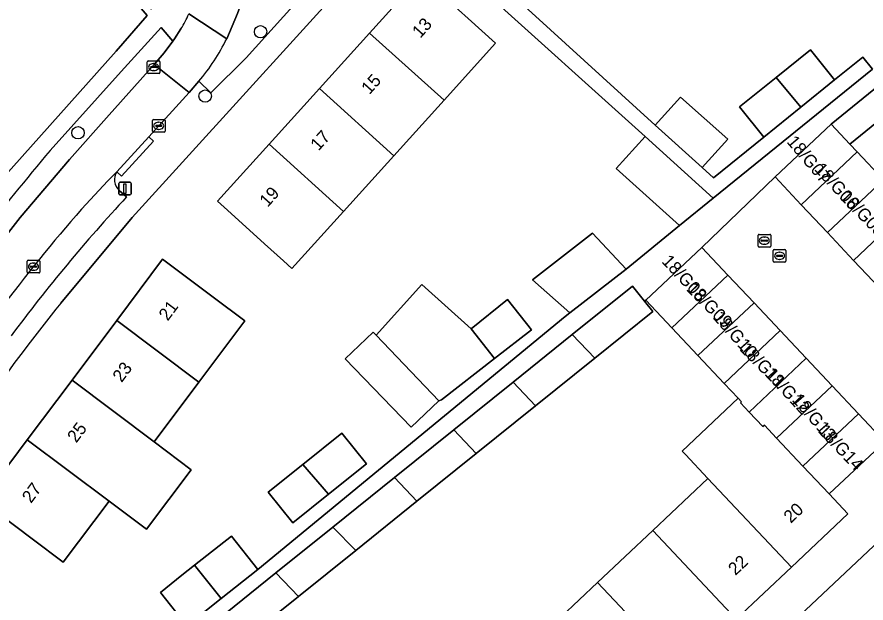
# Model space of a CAD drawing. Extents: x 161881 to 162523, y 381678 to 382381.
# Drawn here: x 162309.8 to 162377, y 381824.1 to 381870.4 of the extents above; entities that cross this region are included whole.
import ezdxf

# ---------------------------------------------------------------- set-up
doc = ezdxf.new("R2010")
doc.units = 0
for name, color, linetype in [('IMGEO_Boom', 7, 'Continuous'), ('IMGEO_Erf', 7, 'Continuous'), ('IMGEO_Groenvoorziening', 7, 'Continuous'), ('IMGEO_Kolk', 7, 'Continuous'), ('IMGEO_Lichtmast', 7, 'Continuous'), ('IMGEO_Pand', 7, 'Continuous'), ('IMGEO_Pand_nummerreeks', 7, 'Continuous'), ('IMGEO_Parkeervlak_open', 7, 'Continuous'), ('IMGEO_Rijbaan_lokaal_open', 7, 'Continuous'), ('IMGEO_Rioolput', 7, 'Continuous'), ('IMGEO_Voetpad_open', 7, 'Continuous')]:
    doc.layers.add(name, color=color, linetype=linetype)

msp = doc.modelspace()

# ---------------------------------------------------------------- linework, layer by layer
at = {"layer": 'IMGEO_Boom'}
for centre in [(162329.077, 381869.231), (162324.693, 381864.143), (162314.637, 381861.242)]:
    msp.add_circle(centre, 0.489, dxfattribs=at)
at = {"layer": 'IMGEO_Erf'}
for points in [[(162308.695, 381857.661), (162317.651, 381867.68), (162320.093, 381870.515), (162317.508, 381873.557), (162311.416, 381880.988), (162315.774, 381884.648), (162315.994, 381884.379), (162316.488, 381884.836), (162316.601, 381884.938), (162316.382, 381885.179), (162318.764, 381887.154), (162318.965, 381886.995), (162319.543, 381887.466), (162319.343, 381887.695), (162320.508, 381888.575), (162315.645, 381894.334), (162318.477, 381896.725), (162315.068, 381901.394), (162281.55, 381876.921), (162275.507, 381885.197)], [(162353.161, 381846.707), (162353.543, 381847.003), (162350.598, 381849.61), (162355.321, 381853.31), (162357.989, 381850.459), (162362.211, 381853.895), (162357.206, 381858.415), (162359.495, 381860.949), (162346.556, 381872.633), (162340.416, 381878.177), (162318.912, 381854.529), (162313.274, 381847.757)], [(162350.544, 381870.731), (162360.3, 381861.84), (162362.297, 381864.051), (162366.048, 381860.746), (162364.011, 381858.49), (162364.905, 381857.683), (162368.889, 381860.901), (162366.965, 381863.284), (162369.857, 381865.619), (162372.561, 381867.803), (162374.485, 381865.419), (162376.709, 381867.214), (162377.479, 381866.261)], [(162380.326, 381864.115), (162375.677, 381860.351), (162376.269, 381859.723), (162378.341, 381857.522)], [(162351.368, 381821.57), (162355.733, 381825.68), (162360.097, 381829.79), (162364.461, 381833.9), (162362.678, 381835.792), (162362.428, 381836.059), (162366.847, 381840.247), (162365.739, 381841.424), (162363.673, 381843.618), (162361.607, 381845.811), (162359.541, 381848.005), (162359.452, 381847.933), (162360.114, 381847.11), (162355.504, 381843.404), (162350.817, 381839.636), (162346.13, 381835.868), (162341.444, 381832.1), (162336.598, 381828.204), (162332.07, 381824.564), (162327.383, 381820.796)], [(162323.239, 381822.253), (162321.148, 381824.898), (162322.854, 381826.247), (162323.856, 381827.039), (162326.779, 381829.352), (162328.871, 381826.707), (162353.161, 381846.707)]]:
    msp.add_lwpolyline(points, dxfattribs=at)
for points in [[(162331.56, 381850.508), (162330.885, 381851.118), (162329.39, 381852.469), (162326.468, 381855.111), (162325.681, 381855.822), (162329.755, 381860.33), (162333.73, 381864.728), (162337.705, 381869.126), (162341.782, 381873.637), (162342.442, 381873.04), (162345.491, 381870.284), (162347.661, 381868.323), (162343.586, 381863.815), (162339.611, 381859.416), (162335.637, 381855.019)], [(162324.194, 381841.527), (162320.657, 381836.81), (162323.58, 381834.6), (162320.051, 381829.895), (162317.092, 381832.114), (162313.465, 381827.278), (162310.999, 381829.127), (162306.999, 381832.127), (162310.626, 381836.963), (162314.163, 381841.68), (162317.701, 381846.396), (162321.328, 381851.233), (162325.328, 381848.233), (162327.821, 381846.363)], [(162335.78, 381843.375), (162337.976, 381845.482), (162338.218, 381845.23), (162341.835, 381849.242), (162345.728, 381845.749), (162348.6, 381848.045), (162350.496, 381845.651), (162347.592, 381843.394), (162343.385, 381840.124), (162343.181, 381840.056), (162340.985, 381837.949)], [(162332.417, 381835.005), (162335.512, 381837.481), (162337.444, 381835.066), (162334.447, 381832.668), (162331.62, 381830.407), (162329.689, 381832.822)], [(162377.552, 381828.547), (162383.149, 381833.811), (162380.574, 381836.724), (162378.448, 381836.809), (162374.061, 381832.677), (162375.536, 381831.111), (162371.061, 381826.897), (162366.697, 381822.787), (162362.333, 381818.677), (162357.968, 381814.567), (162353.605, 381810.457), (162349.24, 381806.347), (162344.875, 381802.236), (162340.402, 381798.024), (162340.265, 381798.17), (162339.511, 381798.971), (162336.964, 381796.572), (162337.718, 381795.771), (162340.037, 381793.265)]]:
    msp.add_lwpolyline(points, close=True, dxfattribs=at)
msp.add_arc((162413.302, 381766.264), 129.022, 140.83, 149.413, dxfattribs=at)
at = {"layer": 'IMGEO_Groenvoorziening'}
for points in [[(162324.203, 381865.309), (162325.146, 381864.385), (162327.942, 381867.176), (162337.02, 381877.264)], [(162328.833, 381875.105), (162327.245, 381870.683), (162326.398, 381868.679)], [(162320.649, 381866.638), (162321.455, 381867.563), (162322.127, 381868.477), (162321.225, 381869.573), (162318.048, 381866.084), (162312.423, 381859.839)], [(162303.292, 381845.82), (162306.611, 381850.151), (162310.057, 381854.543), (162313.959, 381859.114), (162317.095, 381862.667), (162320.649, 381866.638)]]:
    msp.add_lwpolyline(points, dxfattribs=at)
for centre, radius, start, end in [((162310.747, 381876.474), 17.485, 320.31831, 333.52645), ((162591.617, 381627.062), 363.503, 140.18045, 142.96062)]:
    msp.add_arc(centre, radius, start, end, dxfattribs=at)
at = {"layer": 'IMGEO_Kolk'}
for p, q in [((162320.119, 381866.006), (162320.119, 381866.858)), ((162320.194, 381866.932), (162321.046, 381866.932)), ((162320.607, 381866.712), (162320.632, 381866.712)), ((162321.12, 381866.858), (162321.12, 381866.006)), ((162320.378, 381866.426), (162320.378, 381866.438)), ((162320.816, 381866.389), (162320.418, 381866.389)), ((162320.421, 381866.475), (162320.819, 381866.475)), ((162320.63, 381866.152), (162320.605, 381866.152)), ((162320.862, 381866.438), (162320.862, 381866.426)), ((162321.046, 381865.932), (162320.194, 381865.932)), ((162320.52, 381861.36), (162320.52, 381862.212)), ((162320.595, 381862.286), (162321.447, 381862.286)), ((162321.008, 381862.066), (162321.033, 381862.066)), ((162321.521, 381862.212), (162321.521, 381861.36)), ((162320.779, 381861.78), (162320.779, 381861.792)), ((162321.217, 381861.743), (162320.819, 381861.743)), ((162320.822, 381861.829), (162321.22, 381861.829)), ((162321.031, 381861.506), (162321.006, 381861.506)), ((162321.263, 381861.792), (162321.263, 381861.78)), ((162321.447, 381861.286), (162320.595, 381861.286)), ((162369.628, 381851.084), (162369.628, 381851.936)), ((162369.703, 381852.01), (162370.555, 381852.01)), ((162370.629, 381851.936), (162370.629, 381851.084)), ((162369.887, 381851.504), (162369.887, 381851.516)), ((162370.325, 381851.467), (162369.927, 381851.467)), ((162369.93, 381851.553), (162370.328, 381851.553)), ((162370.116, 381851.79), (162370.141, 381851.79)), ((162370.371, 381851.516), (162370.371, 381851.504)), ((162310.61, 381850.228), (162310.61, 381851.08)), ((162310.685, 381851.154), (162311.537, 381851.154)), ((162310.869, 381850.648), (162310.869, 381850.66)), ((162311.307, 381850.611), (162310.909, 381850.611)), ((162310.912, 381850.697), (162311.31, 381850.697)), ((162311.098, 381850.934), (162311.123, 381850.934)), ((162311.353, 381850.66), (162311.353, 381850.648)), ((162311.611, 381851.08), (162311.611, 381850.228)), ((162370.555, 381851.01), (162369.703, 381851.01)), ((162370.139, 381851.23), (162370.114, 381851.23)), ((162311.537, 381850.154), (162310.685, 381850.154)), ((162311.121, 381850.374), (162311.096, 381850.374))]:
    msp.add_line(p, q, dxfattribs=at)
for points in [[(162320.119, 381866.006), (162320.119, 381866.858)], [(162320.194, 381866.932), (162321.046, 381866.932)], [(162321.12, 381866.858), (162321.12, 381866.006)], [(162321.046, 381865.932), (162320.194, 381865.932)], [(162320.52, 381861.36), (162320.52, 381862.212)], [(162320.595, 381862.286), (162321.447, 381862.286)], [(162321.521, 381862.212), (162321.521, 381861.36)], [(162321.447, 381861.286), (162320.595, 381861.286)], [(162369.628, 381851.084), (162369.628, 381851.936)], [(162369.703, 381852.01), (162370.555, 381852.01)], [(162370.629, 381851.936), (162370.629, 381851.084)], [(162310.61, 381850.228), (162310.61, 381851.08)], [(162310.685, 381851.154), (162311.537, 381851.154)], [(162311.611, 381851.08), (162311.611, 381850.228)], [(162370.555, 381851.01), (162369.703, 381851.01)], [(162311.537, 381850.154), (162310.685, 381850.154)]]:
    msp.add_lwpolyline(points, dxfattribs=at)
for centre, radius, start, end in [((162320.196, 381866.856), 0.0765, 91.55205, 178.44795), ((162320.196, 381866.856), 0.0765, 91.55205, 178.44795), ((162321.044, 381866.856), 0.0765, 1.55205, 88.44795), ((162321.044, 381866.856), 0.0765, 1.55205, 88.44795), ((162320.418, 381866.435), 0.0403, 85.87752, 175.75265), ((162320.415, 381866.425), 0.0366, 178.93798, 274.71019), ((162320.819, 381866.432), 0.043, 264.86636, 352.45326), ((162320.823, 381866.437), 0.0386, 1.73085, 96.63898), ((162320.196, 381866.008), 0.0765, 181.55205, 268.44795), ((162320.196, 381866.008), 0.0765, 181.55205, 268.44795), ((162321.044, 381866.008), 0.0765, 271.55205, 358.44795), ((162321.044, 381866.008), 0.0765, 271.55205, 358.44795), ((162320.597, 381862.21), 0.0765, 91.55205, 178.44795), ((162320.597, 381862.21), 0.0765, 91.55205, 178.44795), ((162321.445, 381862.21), 0.0765, 1.55205, 88.44795), ((162321.445, 381862.21), 0.0765, 1.55205, 88.44795), ((162320.597, 381861.362), 0.0765, 181.55205, 268.44795), ((162320.597, 381861.362), 0.0765, 181.55205, 268.44795), ((162320.819, 381861.789), 0.0403, 85.87752, 175.75265), ((162320.816, 381861.779), 0.0366, 178.93798, 274.71019), ((162321.22, 381861.786), 0.043, 264.86636, 352.45326), ((162321.224, 381861.791), 0.0386, 1.73085, 96.63898), ((162321.445, 381861.362), 0.0765, 271.55205, 358.44795), ((162321.445, 381861.362), 0.0765, 271.55205, 358.44795), ((162369.705, 381851.934), 0.0765, 91.55205, 178.44795), ((162369.705, 381851.934), 0.0765, 91.55205, 178.44795), ((162370.553, 381851.934), 0.0765, 1.55205, 88.44795), ((162370.553, 381851.934), 0.0765, 1.55205, 88.44795), ((162369.927, 381851.513), 0.0403, 85.87752, 175.75265), ((162369.924, 381851.503), 0.0366, 178.93798, 274.71019), ((162370.328, 381851.51), 0.043, 264.86636, 352.45326), ((162370.332, 381851.515), 0.0386, 1.73085, 96.63898), ((162310.687, 381851.078), 0.0765, 91.55205, 178.44795), ((162310.687, 381851.078), 0.0765, 91.55205, 178.44795), ((162310.909, 381850.657), 0.0403, 85.87752, 175.75265), ((162310.906, 381850.647), 0.0366, 178.93798, 274.71019), ((162311.31, 381850.654), 0.043, 264.86636, 352.45326), ((162311.314, 381850.659), 0.0386, 1.73085, 96.63898), ((162311.535, 381851.078), 0.0765, 1.55205, 88.44795), ((162311.535, 381851.078), 0.0765, 1.55205, 88.44795), ((162369.705, 381851.086), 0.0765, 181.55205, 268.44795), ((162369.705, 381851.086), 0.0765, 181.55205, 268.44795), ((162370.553, 381851.086), 0.0765, 271.55205, 358.44795), ((162370.553, 381851.086), 0.0765, 271.55205, 358.44795), ((162310.687, 381850.23), 0.0765, 181.55205, 268.44795), ((162310.687, 381850.23), 0.0765, 181.55205, 268.44795), ((162311.535, 381850.23), 0.0765, 271.55205, 358.44795), ((162311.535, 381850.23), 0.0765, 271.55205, 358.44795)]:
    msp.add_arc(centre, radius, start, end, dxfattribs=at)
for centre, major_axis, ratio, start_param, end_param in [((162320.606, 381866.432), (-0.387, 0.002), 0.722429, 4.712389, 7.853982), ((162320.631, 381866.432), (-0.39, 0.002), 0.717154, 1.570796, 4.712389), ((162321.007, 381861.786), (-0.387, 0.002), 0.722429, 4.712389, 7.853982), ((162321.032, 381861.786), (-0.39, 0.002), 0.717154, 1.570796, 4.712389), ((162370.115, 381851.51), (-0.387, 0.002), 0.722429, 4.712389, 7.853982), ((162370.14, 381851.51), (-0.39, 0.002), 0.717154, 1.570796, 4.712389), ((162311.097, 381850.654), (-0.387, 0.002), 0.722429, 4.712389, 7.853982), ((162311.122, 381850.654), (-0.39, 0.002), 0.717154, 1.570796, 4.712389)]:
    msp.add_ellipse(centre, major_axis=major_axis, ratio=ratio, start_param=start_param, end_param=end_param, dxfattribs=at)
at = {"layer": 'IMGEO_Lichtmast'}
for p, q in [((162317.953, 381857.322), (162318.743, 381857.322)), ((162318.743, 381857.322), (162317.953, 381857.322)), ((162317.853, 381856.422), (162317.853, 381857.222)), ((162317.853, 381857.222), (162317.853, 381856.422)), ((162318.843, 381857.222), (162318.843, 381856.422)), ((162318.843, 381856.422), (162318.843, 381857.222)), ((162318.743, 381856.322), (162317.953, 381856.322)), ((162317.953, 381856.322), (162318.743, 381856.322))]:
    msp.add_line(p, q, dxfattribs=at)
msp.add_lwpolyline([(162318.273, 381857.197), (162318.423, 381857.197), (162318.423, 381856.447), (162318.273, 381856.447), (162318.273, 381857.197)], dxfattribs=at)
for centre, start, end in [((162317.953, 381857.222), 90, 180), ((162317.953, 381857.222), 90, 180), ((162318.743, 381857.222), 0, 90), ((162318.743, 381857.222), 360, 90), ((162317.953, 381856.422), 180, 270), ((162317.953, 381856.422), 180, 270), ((162318.743, 381856.422), 270, 0), ((162318.743, 381856.422), 270, 0)]:
    msp.add_arc(centre, 0.1, start, end, dxfattribs=at)
at = {"layer": 'IMGEO_Pand'}
for points in [[(162345.491, 381870.284), (162342.442, 381873.04), (162341.782, 381873.637), (162337.705, 381869.126), (162343.586, 381863.815), (162347.661, 381868.323)], [(162333.73, 381864.728), (162339.611, 381859.416), (162343.586, 381863.815), (162337.705, 381869.126)], [(162369.857, 381865.619), (162371.811, 381863.261), (162374.485, 381865.419), (162372.561, 381867.803)], [(162369.857, 381865.619), (162366.965, 381863.284), (162368.889, 381860.901), (162371.811, 381863.261)], [(162378.844, 381865.687), (162374.196, 381861.923), (162375.677, 381860.351), (162380.326, 381864.115)], [(162333.73, 381864.728), (162329.755, 381860.33), (162335.637, 381855.019), (162339.611, 381859.416)], [(162364.011, 381858.49), (162366.048, 381860.746), (162362.297, 381864.051), (162360.3, 381861.84)], [(162376.269, 381859.723), (162375.677, 381860.351), (162374.196, 381861.923), (162369.767, 381857.752), (162371.839, 381855.551)], [(162362.211, 381853.895), (162364.887, 381856.08), (162359.495, 381860.949), (162357.206, 381858.415)], [(162335.637, 381855.019), (162329.755, 381860.33), (162325.681, 381855.822), (162326.468, 381855.111), (162329.39, 381852.469), (162330.885, 381851.118), (162331.56, 381850.508)], [(162376.269, 381859.723), (162371.839, 381855.551), (162373.912, 381853.351), (162378.341, 381857.522)], [(162375.984, 381851.15), (162380.413, 381855.321), (162378.341, 381857.522), (162373.912, 381853.351)], [(162382.485, 381853.121), (162382.003, 381853.632), (162380.413, 381855.321), (162375.984, 381851.15), (162378.057, 381848.95)], [(162353.543, 381847.003), (162357.989, 381850.459), (162355.321, 381853.31), (162350.598, 381849.61)], [(162361.607, 381845.811), (162366.04, 381849.985), (162363.974, 381852.179), (162359.541, 381848.005)], [(162317.701, 381846.396), (162324.194, 381841.527), (162327.821, 381846.363), (162325.328, 381848.233), (162321.328, 381851.233)], [(162361.607, 381845.811), (162363.673, 381843.618), (162368.105, 381847.792), (162366.04, 381849.985)], [(162345.728, 381845.749), (162341.835, 381849.242), (162338.218, 381845.23), (162343.181, 381840.056), (162343.385, 381840.124), (162347.592, 381843.394)], [(162360.114, 381847.11), (162359.452, 381847.933), (162358.498, 381849.12), (162353.73, 381845.286), (162355.504, 381843.404)], [(162348.6, 381848.045), (162345.728, 381845.749), (162347.592, 381843.394), (162350.496, 381845.651)], [(162370.171, 381845.598), (162368.105, 381847.792), (162363.673, 381843.618), (162365.739, 381841.424)], [(162317.701, 381846.396), (162314.163, 381841.68), (162320.657, 381836.81), (162324.194, 381841.527)], [(162338.218, 381845.23), (162337.976, 381845.482), (162335.78, 381843.375), (162340.985, 381837.949), (162343.181, 381840.056)], [(162353.73, 381845.286), (162349.043, 381841.518), (162350.817, 381839.636), (162355.504, 381843.404)], [(162372.237, 381843.405), (162370.171, 381845.598), (162365.739, 381841.424), (162366.847, 381840.247), (162367.11, 381839.968), (162367.028, 381839.892), (162367.723, 381839.152)], [(162372.237, 381843.405), (162367.723, 381839.152), (162368.805, 381838.001), (162368.93, 381838.118), (162369.896, 381837.094), (162374.285, 381841.229)], [(162320.657, 381836.81), (162314.163, 381841.68), (162310.626, 381836.963), (162317.092, 381832.114), (162320.051, 381829.895), (162323.58, 381834.6)], [(162349.043, 381841.518), (162344.356, 381837.75), (162346.13, 381835.868), (162350.817, 381839.636)], [(162371.978, 381834.886), (162376.367, 381839.019), (162374.285, 381841.229), (162369.896, 381837.094)], [(162371.978, 381834.886), (162369.896, 381837.094), (162368.93, 381838.118), (162368.805, 381838.001), (162367.723, 381839.152), (162367.028, 381839.892), (162367.11, 381839.968), (162366.847, 381840.247), (162362.428, 381836.059), (162362.678, 381835.792), (162364.461, 381833.9), (162371.061, 381826.897), (162375.536, 381831.111), (162374.061, 381832.677)], [(162371.978, 381834.886), (162374.061, 381832.677), (162378.448, 381836.809), (162376.367, 381839.019)], [(162335.512, 381837.481), (162332.417, 381835.005), (162334.447, 381832.668), (162337.444, 381835.066)], [(162339.67, 381833.983), (162341.444, 381832.1), (162346.13, 381835.868), (162344.356, 381837.75)], [(162310.626, 381836.963), (162306.999, 381832.127), (162310.999, 381829.127), (162313.465, 381827.278), (162317.092, 381832.114)], [(162332.417, 381835.005), (162329.689, 381832.822), (162331.62, 381830.407), (162334.447, 381832.668)], [(162339.67, 381833.983), (162334.797, 381830.064), (162336.598, 381828.204), (162341.444, 381832.1)], [(162364.461, 381833.9), (162360.097, 381829.79), (162366.697, 381822.787), (162371.061, 381826.897)], [(162330.296, 381826.446), (162332.07, 381824.564), (162336.598, 381828.204), (162334.797, 381830.064)], [(162362.333, 381818.677), (162366.697, 381822.787), (162360.097, 381829.79), (162355.733, 381825.68)], [(162326.779, 381829.352), (162323.856, 381827.039), (162325.971, 381824.413), (162328.871, 381826.707)], [(162325.971, 381824.413), (162323.856, 381827.039), (162322.854, 381826.247), (162321.148, 381824.898), (162323.239, 381822.253)], [(162325.609, 381822.678), (162327.383, 381820.796), (162332.07, 381824.564), (162330.296, 381826.446)], [(162362.333, 381818.677), (162355.733, 381825.68), (162351.368, 381821.57), (162357.968, 381814.567)]]:
    msp.add_lwpolyline(points, close=True, dxfattribs=at)
at = {"layer": 'IMGEO_Parkeervlak_open'}
for points in [[(162317.714, 381858.155), (162316.997, 381857.442), (162314.904, 381855.188)], [(162318.479, 381856.168), (162317.896, 381856.676)]]:
    msp.add_lwpolyline(points, dxfattribs=at)
for centre, radius, start, end in [((162318.634, 381857.517), 1.119, 145.27106, 228.75959), ((162415.221, 381766.452), 131.939, 137.15809, 143.35927), ((162424.966, 381759.231), 146.019, 138.91675, 147.00635)]:
    msp.add_arc(centre, radius, start, end, dxfattribs=at)
at = {"layer": 'IMGEO_Rijbaan_lokaal_open'}
for points in [[(162323.403, 381870.644), (162326.398, 381868.679), (162327.245, 381870.683), (162328.833, 381875.105)], [(162326.398, 381868.679), (162323.403, 381870.644)], [(162322.78, 381869.453), (162322.262, 381868.661), (162322.127, 381868.477), (162321.455, 381867.563), (162320.649, 381866.638), (162323.422, 381864.435), (162324.203, 381865.309)], [(162314.904, 381855.188), (162316.997, 381857.442), (162317.714, 381858.155), (162320.231, 381860.917), (162323.422, 381864.435), (162320.649, 381866.638), (162317.095, 381862.667), (162313.959, 381859.114), (162310.057, 381854.543), (162306.611, 381850.151), (162303.292, 381845.82)], [(162377.552, 381828.547), (162340.037, 381793.265), (162339.247, 381792.69), (162337.86, 381791.68), (162337.099, 381792.618), (162336.934, 381792.508), (162339.301, 381788.958), (162331.668, 381784.055), (162329.445, 381787.515), (162325.988, 381783.891), (162321.869, 381779.571), (162318.379, 381775.91), (162318.58, 381775.651), (162317.309, 381774.987), (162317.648, 381774.288), (162309.959, 381770.404), (162312.53, 381763.243)]]:
    msp.add_lwpolyline(points, dxfattribs=at)
msp.add_lwpolyline([(162384.274, 381842.348), (162382.202, 381844.549), (162380.129, 381846.749), (162378.057, 381848.95), (162375.984, 381851.15), (162373.912, 381853.351), (162371.839, 381855.551), (162369.767, 381857.752), (162363.974, 381852.179), (162366.04, 381849.985), (162368.105, 381847.792), (162370.171, 381845.598), (162372.237, 381843.405), (162374.285, 381841.229), (162376.367, 381839.019), (162378.448, 381836.809), (162380.574, 381836.724), (162383.149, 381833.811), (162386.615, 381837.08), (162384.06, 381839.873)], close=True, dxfattribs=at)
for centre, radius, start, end in [((162311.472, 381876.126), 13.13, 329.45242, 335.32036), ((162310.747, 381876.474), 17.485, 320.31831, 333.52645), ((162424.966, 381759.231), 146.019, 138.91675, 147.00635)]:
    msp.add_arc(centre, radius, start, end, dxfattribs=at)
at = {"layer": 'IMGEO_Rioolput'}
for p, q in [((162368.426, 381852.28), (162368.426, 381853.132)), ((162368.501, 381853.206), (162369.353, 381853.206)), ((162368.685, 381852.7), (162368.685, 381852.712)), ((162369.123, 381852.663), (162368.725, 381852.663)), ((162368.728, 381852.749), (162369.126, 381852.749)), ((162368.914, 381852.986), (162368.939, 381852.986)), ((162369.169, 381852.712), (162369.169, 381852.7)), ((162369.427, 381853.132), (162369.427, 381852.28)), ((162369.353, 381852.206), (162368.501, 381852.206)), ((162368.937, 381852.426), (162368.912, 381852.426))]:
    msp.add_line(p, q, dxfattribs=at)
for points in [[(162368.426, 381852.28), (162368.426, 381853.132)], [(162368.501, 381853.206), (162369.353, 381853.206)], [(162369.427, 381853.132), (162369.427, 381852.28)], [(162369.353, 381852.206), (162368.501, 381852.206)]]:
    msp.add_lwpolyline(points, dxfattribs=at)
for centre, radius, start, end in [((162368.503, 381853.13), 0.0765, 91.55205, 178.44795), ((162368.503, 381853.13), 0.0765, 91.55205, 178.44795), ((162368.725, 381852.709), 0.0403, 85.87752, 175.75265), ((162368.722, 381852.699), 0.0366, 178.93798, 274.71019), ((162369.126, 381852.706), 0.043, 264.86636, 352.45326), ((162369.13, 381852.711), 0.0386, 1.73085, 96.63898), ((162369.351, 381853.13), 0.0765, 1.55205, 88.44795), ((162369.351, 381853.13), 0.0765, 1.55205, 88.44795), ((162368.503, 381852.282), 0.0765, 181.55205, 268.44795), ((162368.503, 381852.282), 0.0765, 181.55205, 268.44795), ((162369.351, 381852.282), 0.0765, 271.55205, 358.44795), ((162369.351, 381852.282), 0.0765, 271.55205, 358.44795)]:
    msp.add_arc(centre, radius, start, end, dxfattribs=at)
for centre, major_axis, ratio, start_param, end_param in [((162368.913, 381852.706), (-0.387, 0.002), 0.722429, 4.712389, 7.853982), ((162368.938, 381852.706), (-0.39, 0.002), 0.717154, 1.570796, 4.712389)]:
    msp.add_ellipse(centre, major_axis=major_axis, ratio=ratio, start_param=start_param, end_param=end_param, dxfattribs=at)
at = {"layer": 'IMGEO_Voetpad_open'}
for points in [[(162354.947, 381898.752), (162355.663, 381897.834), (162349.335, 381892.545), (162350.082, 381891.85), (162347.971, 381889.246), (162341.733, 381882.383), (162338.101, 381885.656), (162333.045, 381881.362), (162332.821, 381881.145), (162337.02, 381877.264), (162327.942, 381867.176), (162325.146, 381864.385), (162324.203, 381865.309), (162323.422, 381864.435), (162320.231, 381860.917), (162320.6, 381860.581), (162318.083, 381857.819), (162317.714, 381858.155)], [(162323.967, 381873.987), (162320.411, 381871.008), (162318.587, 381873.075), (162318.649, 381873.357), (162312.385, 381880.712), (162315.826, 381883.619), (162316.82, 381884.434), (162316.488, 381884.836), (162315.994, 381884.379), (162315.774, 381884.648), (162311.416, 381880.988), (162317.508, 381873.557), (162320.093, 381870.515), (162317.651, 381867.68), (162308.695, 381857.661), (162297.241, 381842.76), (162296.259, 381841.323), (162293.145, 381836.115), (162290.13, 381831.074), (162292.698, 381829.565), (162295.774, 381834.818), (162296.354, 381835.769), (162298.878, 381839.59)], [(162313.274, 381847.757), (162318.912, 381854.529), (162340.416, 381878.177)], [(162312.423, 381859.839), (162318.048, 381866.084), (162321.225, 381869.573), (162322.127, 381868.477)], [(162322.127, 381868.477), (162322.262, 381868.661), (162322.78, 381869.453)], [(162377.479, 381866.261), (162364.887, 381856.08), (162362.211, 381853.895), (162357.989, 381850.459), (162353.543, 381847.003), (162353.161, 381846.707), (162328.871, 381826.707), (162325.971, 381824.413), (162323.239, 381822.253)], [(162325.609, 381822.678), (162330.296, 381826.446), (162334.797, 381830.064), (162339.67, 381833.983), (162344.356, 381837.75), (162349.043, 381841.518), (162353.73, 381845.286), (162358.498, 381849.12), (162359.452, 381847.933), (162359.541, 381848.005), (162363.974, 381852.179), (162369.767, 381857.752), (162374.196, 381861.923), (162378.844, 381865.687)], [(162317.896, 381856.676), (162318.479, 381856.168)]]:
    msp.add_lwpolyline(points, dxfattribs=at)
for points in [[(162350.544, 381870.731), (162348.249, 381872.815), (162345.341, 381875.564), (162341.358, 381879.213), (162340.416, 381878.177), (162346.556, 381872.633), (162359.495, 381860.949), (162364.887, 381856.08), (162377.479, 381866.261), (162376.709, 381867.214), (162374.485, 381865.419), (162371.811, 381863.261), (162368.889, 381860.901), (162364.905, 381857.683), (162364.011, 381858.49), (162360.3, 381861.84)], [(162320.231, 381860.917), (162317.714, 381858.155), (162318.083, 381857.819), (162320.6, 381860.581)]]:
    msp.add_lwpolyline(points, close=True, dxfattribs=at)
for centre, radius, start, end in [((162311.472, 381876.126), 13.13, 329.45242, 335.32036), ((162591.617, 381627.062), 363.503, 140.18045, 142.96062), ((162318.634, 381857.517), 1.119, 145.27106, 228.75959), ((162415.221, 381766.452), 131.939, 137.15809, 143.35927), ((162413.302, 381766.264), 129.022, 140.83, 149.413)]:
    msp.add_arc(centre, radius, start, end, dxfattribs=at)

# ---------------------------------------------------------------- texts
at = {"layer": 'IMGEO_Pand_nummerreeks'}
for s, rotation, p in [('13', 47.89308, (162341.71, 381868.666)), ('15', 47.89308, (162337.685, 381864.212)), ('17', 47.89308, (162333.659, 381859.758)), ('18/G07', 310.34175, (162370.644, 381860.503)), ('18/G06', 312.11704, (162372.829, 381858.326)), ('19', 47.89308, (162329.634, 381855.304)), ('18/G05', 314.19307, (162374.824, 381856.111)), ('18/G08', 313.2643, (162360.747, 381851.03)), ('18/G09', 314.56921, (162362.705, 381848.828)), ('21', 53.13106, (162321.733, 381846.306)), ('18/G10', 311.68222, (162364.802, 381846.608)), ('18/G11', 314.99989, (162366.916, 381844.074)), ('23', 53.13106, (162318.083, 381841.439)), ('18/G12', 312.84704, (162368.895, 381842.138)), ('18/G13', 310.97174, (162371.059, 381840.094)), ('25', 53.13038, (162314.5, 381836.663)), ('18/G14', 313.36342, (162373.106, 381837.628)), ('27', 53.13106, (162310.918, 381831.886)), ('20', 43.28123, (162371.019, 381830.319)), ('22', 43.28133, (162366.635, 381826.19))]:
    msp.add_text(s, height=1, rotation=rotation, dxfattribs=at).set_placement(p)

doc.saveas('drawing.dxf')
